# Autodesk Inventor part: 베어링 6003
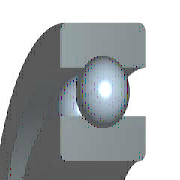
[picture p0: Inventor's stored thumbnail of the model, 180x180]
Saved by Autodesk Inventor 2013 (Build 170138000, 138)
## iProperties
Created: 2012-02
Part Number: 베어링 6003
Material: 강철, 연강
Description: 깊은 그루브 볼 베어링
Document SubType Name: Modeling
Standard: KS B 2023
Designer: mduedu
Standards Organization: KS
Language: ko-KR
Size Designation: 6003 - 17 x 35 x 10
Categories: <MemberInstance><Categories><Category DisplayName="샤프트 부품" InternalName="7f7aeb1f-a693-4053-b835-cee3144e0d98" Mnemonic="SHFT"><Category DisplayName="베어링" Inter
Density: 1 g/cm^3
IsCustomPart: 1
Author: mduedu
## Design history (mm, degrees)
sketch "스케치" dims "d0" = 4.68 (= -0.26 x WD + 0.26 x BD)
  geometry: L1 (2.66, 13)-(7.34, 13); L2 (5, 13)-(5, 10.66); L3 (5, 13)-(5, 15.34); L4 (3.261, 11.434)-(0, 11.434); L5 (0, 8.5)-(10, 8.5); L6 (3.261, 14.566)-(0, 14.566); L7 (0, 17.5)-(10, 17.5); L8 (10, 8.5)-(10, 11.434); L9 (6.739, 11.434)-(10, 11.434); L10 (6.739, 14.566)-(10, 14.566); L11 (10, 17.5)-(10, 14.566); L12 (-1.4, 0)-(8.4, 0) reference; L13 (0, -0.3)-(0, 5.3) reference
  constraints: 22 end point, 4 point on line, 2 collinear, 2 perpendicular, 2 symmetric about line, 1 midpoint, 1 parallel, 14 other
  dimensions: "d9" = 17 diameter of L5 L12 (= WD); "d11" = 35 diameter of L7 L12 (= BD); "d12" = 10 distance between parallel lines of L8 L13 (= KB); "d13" = 22.868 diameter of L9 L12 (= 0.326 x BD + 0.674 x WD)
revolve "본체" stored, may be unused: angle "d6" = 90 deg
revolve "볼" stored, may be unused: angle "d7" = 90 deg
pattern_circular "IDS_ARRAYBALL[SIMPL:T]" dims angle "d3" = 360 deg
body "Solid1"
fillet "모깎기1" dims "d1" = 0.3 (= KRS)
other parameters: "WD" = 17 [user parameter; used in 5 equation terms], "BD" = 35 [user parameter; used in 5 equation terms], "KB" = 10 [user parameter; used in 1 equation term], "KRS" = 0.3 [user parameter; used in 1 equation term], "d4" = 0, "d5" = 0, "d8" = 0, "d14" = 0, "d15" = 0, "BBA" = 0 [user parameter], "BC0" = 3250000 [user parameter], "BC" = 6050000 [user parameter], "BR" = 17.5 (= 0.5 x BD) [user parameter], "WR" = 8.5 (= 0.5 x WD) [user parameter]
